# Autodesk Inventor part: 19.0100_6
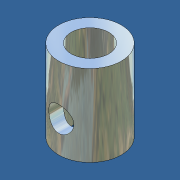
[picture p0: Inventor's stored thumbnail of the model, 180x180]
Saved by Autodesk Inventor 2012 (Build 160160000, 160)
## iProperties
Created: 2011-09
Part Number: 19.0100_6
Material: Steel
Document SubType Name: Modeling
Designer: Administrator
Mass: 4.92646 g
Surface Area: 7.54913 cm^2
Volume: 0.627574 cm^3
Density: 7.85 g/cm^3
Description: BUSHING 10MM OD, 6mm ID FOR HANDLE
Vendor: S
Author: Administrator
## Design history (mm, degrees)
sketch "Sketch1"
  geometry: C1 r 5 at (0, 0); C2 r 3 at (0, 0); 2 further points
  constraints: 2 centre point
  dimensions: "d0" = 10 diameter of C1; "d1" = 6 diameter of C2
extrude "Extrusion1" new body sketch "Sketch1" stored distance "d2" = 13; taper "d3" = 0 deg
sketch "Sketch2"
  geometry: L1 (3, -6.5)-(-3, -6.5) reference; 3 further points
  constraints: 1 midpoint, 1 vertical alignment
  dimensions: "d4" = 5 distance from line of point (0, -1.5) L1
hole "Hole1" sketch "Sketch2" at (0, -1.5) diameter "d5" = 4; stored, may be unused: countersink angle "d9" = 90 deg, drill point angle "d11" = 118 deg; dims "d6" = 6, "d7" = 4, "d8" = 2, "d10" = 8
body "Solid1"
